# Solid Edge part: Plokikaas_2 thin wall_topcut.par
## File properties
Author: KULL
Template: Iso Metric Part.par
Last saved by: KULL
Revision: 9
Application: Solid Edge
Accuracy: 0,990
Face Style: Model Default
Fill Style: Normal
Coef. of Thermal Exp: 0.0
Thermal Conductivity: 0.0
Specific Heat: 0.0
Modulus of Elasticity: 0.0
Poisson's Ratio: 0.0
Yield Stress: 0.0
Ultimate Stress: 0.0
Elongation: 0.0
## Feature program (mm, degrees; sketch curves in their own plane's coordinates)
pattern "unnamed Pattern 1"
pattern "unnamed Pattern 2"
Other named dimensions: "Pattern_1": XDirCount = 5; XDirSpacing = 18 mm | "Pattern_2": XDirCount = 5; XDirSpacing = 18 mm
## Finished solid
Body 1: solid body, 265 faces, 478 edges, 216 vertices.
  Faces by surface: plane 63, cylinder 52, torus 50, offset 40, spline 40, cone 20
  Edges by curve: circle 142, line 120, intersection 116, ellipse 40, curve on surface 30, spline 30
Body 2: sheet body, 1 face, 13 edges, 8 vertices.
  Faces by surface: plane 1
  Edges by curve: circle 9, line 4
Bounding box of the edges (mm; curved faces can reach further): 96.000 x 29.204 x 27.590, from (-48, 15.1609, 37.8813) to (48, 44.3649, 65.4719).
Cylindrical faces by radius (mm): R0.7583 x10, R0.7983 x10, R3 x4, R3.04 x4, R5 x8, R5.04 x8, R7.96 x4, R8 x4
Conical faces (half-angle, radius in mm at the cone's reference point): 0.9869 deg R2.4867 x10, 0.9869 deg R2.5267 x10
Toroidal faces (ring radius, tube radius in mm): R2.1444 r0.4 x10, R2.1444 r0.44 x10, R2.582 r1.7841 x10, R2.582 r1.8241 x10, R3.3542 r4 x5, R3.3542 r4.04 x5
Planar faces by outward normal: +x 2, -x 2, oblique 59
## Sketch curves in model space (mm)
line (36, 34.3873, 57.1877) -> (-36, 34.3873, 57.1877)
line (36, 28.3292, 45.3007) -> (36, 41.2745, 52.7747)
line (36, 26.031, 47.2291) -> (36, 30.6273, 43.3724)
line (36, 26.031, 47.2291) -> (36, 37.0524, 60.3638)
line (36, 40.115, 43.2436) -> (-36, 40.115, 43.2436)
circle centre (-36, 40.115, 43.2436) radius 2
circle centre (-18, 40.115, 43.2436) radius 2
circle centre (0, 40.115, 43.2436) radius 2
circle centre (18, 40.115, 43.2436) radius 2
line (-42, 40.0885, 35.4334) -> (-30, 40.0885, 35.4334)
line (-24, 40.0885, 35.4334) -> (-12, 40.0885, 35.4334)
line (-6, 40.0885, 35.4334) -> (6, 40.0885, 35.4334)
line (12, 40.0885, 35.4334) -> (24, 40.0885, 35.4334)
line (30, 40.0885, 35.4334) -> (42, 40.0885, 35.4334)
line (48, 43.9453, 40.0297) -> (-48, 43.9453, 40.0297)
circle centre (-36, 43.9453, 40.0297) radius 2
circle centre (-18, 43.9453, 40.0297) radius 2
circle centre (0, 43.9453, 40.0297) radius 2
circle centre (18, 43.9453, 40.0297) radius 2
circle centre (36, 43.9453, 40.0297) radius 2
line (48, 21.2893, 49.9025) -> (48, 29.4872, 43.0236)
arc centre (40, 29.4872, 43.0236) radius 8 from (48, 29.4872, 43.0236) through (45.4899, 33.9448, 39.2833) to (40, 35.6155, 37.8813)
line (40, 35.6155, 37.8813) -> (-40, 35.6155, 37.8813)
arc centre (-40, 29.4872, 43.0236) radius 8 from (-40, 35.6155, 37.8813) through (-45.819, 33.6927, 39.4948) to (-48, 29.4872, 43.0236)
line (-48, 29.4872, 43.0236) -> (-48, 21.2893, 49.9025)
arc centre (-40, 21.2893, 49.9025) radius 8 from (-48, 21.2893, 49.9025) through (-45.4899, 16.8317, 53.6428) to (-40, 15.1609, 55.0448)
line (-40, 15.1609, 55.0448) -> (40, 15.1609, 55.0448)
arc centre (40, 21.2893, 49.9025) radius 8 from (40, 15.1609, 55.0448) through (45.819, 17.0838, 53.4313) to (48, 21.2893, 49.9025)
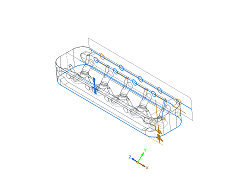
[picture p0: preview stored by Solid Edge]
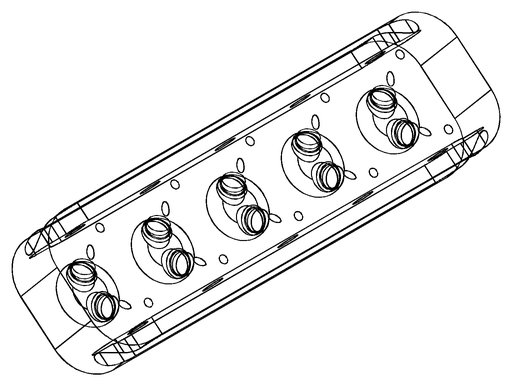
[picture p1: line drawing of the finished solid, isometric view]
